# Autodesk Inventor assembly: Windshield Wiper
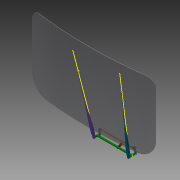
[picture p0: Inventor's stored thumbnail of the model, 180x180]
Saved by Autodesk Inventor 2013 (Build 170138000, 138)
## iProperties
Created: 2006-03
Part Number: Windshield Wiper
Document SubType Name: Assembly
Designer: debonom
Mass: 23655.8 g
Surface Area: 27679.2 cm^2
Volume: 10299.3 cm^3
Density: 2.29683 g/cm^3
Author: debonom
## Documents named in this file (9)
- C:\Users\boganb\Documents\B2 Design\Goodyear\2013 Tutorial Files\Dynamic Simulation 4\Windshield Wiper.iam
- C:\Users\boganb\Documents\B2 Design\Goodyear\2013 Tutorial Files\Dynamic Simulation 4\Components\Windshield.ipt
- C:\Users\boganb\Documents\B2 Design\Goodyear\2013 Tutorial Files\Dynamic Simulation 4\Components\Brush.iam
- C:\Users\boganb\Documents\B2 Design\Goodyear\2013 Tutorial Files\Dynamic Simulation 4\Components\Crank Sway.ipt
- C:\Users\boganb\Documents\B2 Design\Goodyear\2013 Tutorial Files\Dynamic Simulation 4\Components\Crank Motor.ipt
- C:\Users\boganb\Documents\B2 Design\Goodyear\2013 Tutorial Files\Dynamic Simulation 4\Components\Wiper base Left.iam
- C:\Users\boganb\Documents\B2 Design\Goodyear\2013 Tutorial Files\Dynamic Simulation 4\Components\Wiper base Right.iam
- C:\Users\boganb\Documents\B2 Design\Goodyear\2013 Tutorial Files\Dynamic Simulation 4\Components\Crank Motor.iam
- C:\Users\boganb\Documents\B2 Design\Goodyear\2013 Tutorial Files\Dynamic Simulation 4\Components\Frame Wiper.ipt
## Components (9 placed, 7 different names)
1. Frame Wiper:1 — Mate:1, Mate:2, Mate:3, Mate:11, Mate:9, Mate:14, Mate:15, Angle DRIVE, Mate:16, Mate:19
2. Crank Motor:2 [sub-assembly] — Mate:15, Angle DRIVE, Mate:16, Mate:17
3. Wiper base Left:1 [sub-assembly] — Mate:14, Mate:4, Mate:5, Angle:2, Insert:2, Insert:3, Mate:19
4. Brush:1 [sub-assembly] — Mate:4, Mate:5, Angle:2
5. Wiper base Right:1 [sub-assembly] — Mate:11, Mate:9, Mate:12, Mate:13, Angle:3, Mate:18
6. Brush:2 [sub-assembly] — Mate:12, Mate:13, Angle:3
7. Crank Motor:1 — Insert:3, Mate:17
8. Crank Sway:1 — Insert:2, Mate:18
9. Windshield:1 — Mate:1, Mate:2, Mate:3
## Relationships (20: Mate 15, Angle 3, Insert 2)
- Mate:1: Frame Wiper:1 ↔ Windshield:1
- Mate:2: Frame Wiper:1 ↔ Windshield:1
- Mate:3: Frame Wiper:1 ↔ Windshield:1
- Mate:14: Frame Wiper:1 ↔ Wiper base Left:1
- Mate:4: Wiper base Left:1 ↔ Brush:1
- Mate:5: Wiper base Left:1 ↔ Brush:1
- Angle:2: Wiper base Left:1 ↔ Brush:1
- Mate:11: Frame Wiper:1 ↔ Wiper base Right:1
- Mate:9: Frame Wiper:1 ↔ Wiper base Right:1
- Mate:12: Wiper base Right:1 ↔ Brush:2
- Mate:13: Wiper base Right:1 ↔ Brush:2
- Angle:3: Wiper base Right:1 ↔ Brush:2
- Insert:2: Wiper base Left:1 ↔ Crank Sway:1
- Insert:3: Wiper base Left:1 ↔ Crank Motor:1
- Mate:15: Frame Wiper:1 ↔ Crank Motor:2
- Angle DRIVE: Frame Wiper:1 ↔ Crank Motor:2
- Mate:16: Frame Wiper:1 ↔ Crank Motor:2
- Mate:17: Crank Motor:2 ↔ Crank Motor:1
- Mate:18: Wiper base Right:1 ↔ Crank Sway:1
- Mate:19: Frame Wiper:1 ↔ Wiper base Left:1
